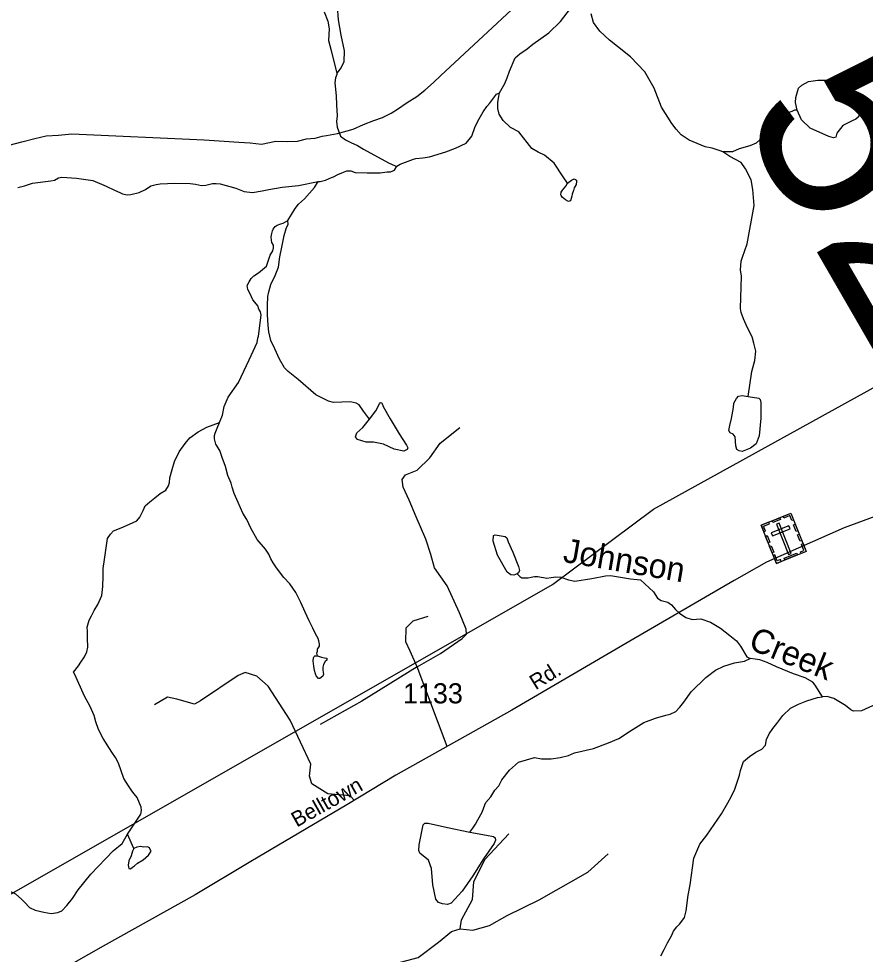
# Model space of a CAD drawing. Extents: x 2056842 to 2160602, y 826753 to 1016856.
# Drawn here: x 2087343 to 2092594, y 896145 to 901949 of the extents above; entities that cross this region are included whole.
import ezdxf

# ---------------------------------------------------------------- set-up
doc = ezdxf.new("R2010")
doc.units = 0
for name, color, linetype in [('Exist Cultural Cemetery CELL', 7, 'Continuous'), ('Exist Hydrographic Creek Single Shore', 7, 'Continuous'), ('Exist Hydrographic Creek Single Shore Label', 7, 'Continuous'), ('Exist Hydrographic Misc Water Feature', 7, 'Continuous'), ('Exist Railroad Mainline', 7, 'Continuous'), ('Exist Road Non-System Type 51', 7, 'Continuous'), ('Exist Road Secondary Structure Standard Bridge Number Label', 7, 'Continuous'), ('Exist Road Secondary Type 51 Attributed', 7, 'Continuous'), ('Exist Road Secondary Type 51 Label', 7, 'Continuous'), ('Exist Road Secondary Type 51 Number Label', 7, 'Continuous'), ('Exist Utilities Electrical Transmission Line', 7, 'Continuous')]:
    doc.layers.add(name, color=color, linetype=linetype)

msp = doc.modelspace()

# ---------------------------------------------------------------- linework, layer by layer
at = {"layer": 'Exist Cultural Cemetery CELL'}
for points in [[(2091948.1, 898806.6), (2092132.9, 898880.6), (2092227.5, 898644.1), (2092042.7, 898570.2)], [(2091964.2, 898766.4), (2091974.7, 898770.6), (2091962.8, 898800.5), (2092000.4, 898815.5), (2091996.3, 898825.9), (2091948.1, 898806.6)], [(2092016.9, 898834.1), (2092065, 898853.3), (2092069.2, 898842.8), (2092021.1, 898823.5)], [(2092149.1, 898840.3), (2092138.6, 898836.1), (2092126.6, 898866), (2092089, 898850.9), (2092084.8, 898861.3), (2092133, 898880.5)], [(2092011.3, 898758.6), (2092018.2, 898741.2), (2092127.5, 898785), (2092120.6, 898802.3)], [(2092060.2, 898819.9), (2092042.9, 898813), (2092118.2, 898624.7), (2092135.5, 898631.6)], [(2092165.7, 898768.2), (2092149.6, 898808.4), (2092160.2, 898812.7), (2092176.2, 898772.5)], [(2091991.7, 898697.5), (2091975.6, 898737.7), (2091986.2, 898742), (2092002.3, 898701.8)], [(2092190.1, 898707), (2092174, 898747.2), (2092184.6, 898751.5), (2092200.7, 898711.2)], [(2092016.7, 898635.1), (2092000.6, 898675.3), (2092011.2, 898679.6), (2092027.3, 898639.3)], [(2092196.8, 898631.8), (2092192.5, 898642.5), (2092212.9, 898650.7), (2092197.9, 898688.2), (2092208.3, 898692.3), (2092227.5, 898644.1)], [(2092073.4, 898582.5), (2092069.1, 898593.2), (2092048.7, 898585), (2092033.7, 898622.5), (2092023.3, 898618.4), (2092042.6, 898570.2)], [(2092091.8, 898602.2), (2092170.6, 898633.7), (2092174.8, 898623.1), (2092096, 898591.6)]]:
    msp.add_lwpolyline(points, close=True, dxfattribs=at)
at = {"layer": 'Exist Hydrographic Creek Single Shore'}
for points in [[(2090325.3, 901488), (2090357.3, 901546.1), (2090373.1, 901582.1), (2090387.1, 901622.2), (2090422.7, 901706.3), (2090450.6, 901730.4), (2090496.6, 901762.5), (2090532.4, 901790.7), (2090631.4, 901861), (2090703.7, 901932.1), (2090833.5, 902103.5), (2090877.1, 902183.6), (2090923.1, 902251.7), (2090956.9, 902297.9), (2090986.8, 902319.9), (2091030.7, 902346), (2091062.5, 902384.2)], [(2089688.9, 901034), (2089709, 901046.1), (2089790.8, 901076.4), (2089806.8, 901080.4), (2089850.5, 901084.9), (2089891.6, 901092.4), (2089992.7, 901123.6), (2090051.3, 901146.1), (2090118.7, 901176), (2090154.3, 901219.5), (2090174, 901279.6), (2090199.8, 901327.7), (2090223.8, 901371.6), (2090245.6, 901403.7), (2090263.6, 901421.8), (2090287.6, 901455.8), (2090307.5, 901479.9), (2090325.3, 901488)], [(2089201.2, 900938.6), (2089213.3, 900938.6), (2089245.1, 900946.7), (2089283.3, 900962.8), (2089295.2, 900966.9), (2089323, 900982.9), (2089357.1, 900997), (2089379, 901005.1), (2089403, 901005.1), (2089429.1, 900995.3), (2089505.1, 900993.4), (2089585.1, 900991.7), (2089629, 900997.8), (2089649.1, 900997.9), (2089673.1, 901008.1), (2089688.9, 901034)], [(2087337.5, 900900.7), (2087377.5, 900912.8), (2087427.3, 900929), (2087541.3, 900943.4), (2087565.3, 900947.4), (2087589.3, 900961.5), (2087609.2, 900965.5), (2087701.3, 900959.9), (2087801.4, 900944.2), (2087885.3, 900909.7), (2087937.7, 900884.7), (2087968.9, 900869.7), (2087986.3, 900862.2), (2088016.3, 900856), (2088037.8, 900858.9), (2088089.7, 900871.1), (2088129.6, 900889.2), (2088161.4, 900911.3), (2088195.5, 900919.4), (2088219.5, 900923.5), (2088310.7, 900928.4), (2088405.5, 900925.9), (2088439.5, 900922.2), (2088476.6, 900914.7), (2088504, 900915.9), (2088543.9, 900927.1), (2088567.6, 900927.1), (2088591.4, 900924.6), (2088689.4, 900896.9), (2088741.5, 900877.2), (2088793.6, 900871.3), (2088853.5, 900881.5), (2088893.5, 900889.6), (2088977.3, 900903.8), (2089079.2, 900914.2), (2089201.2, 900938.6)], [(2092329.5, 897743), (2092284.3, 897814.1), (2092268.3, 897834.1), (2092222.3, 897860), (2092148.3, 897883.9), (2092044.2, 897927.4), (2091986, 897955.5), (2091940.1, 897971.2), (2091912, 897975.1), (2091879.9, 897979)], [(2093100.5, 897591), (2093063, 897610.9), (2093022.8, 897652.5), (2092990.8, 897676.5), (2092936.7, 897692.4), (2092874.5, 897716.3), (2092818.5, 897722), (2092766.6, 897717.9), (2092683.8, 897706.8), (2092570.3, 897654.4), (2092521.6, 897653.1), (2092505.4, 897660.6), (2092471.7, 897688.1), (2092399.4, 897731.7), (2092358.2, 897744.2), (2092329.5, 897743)]]:
    msp.add_lwpolyline(points, dxfattribs=at)
at = {"layer": 'Exist Hydrographic Misc Water Feature'}
msp.add_line((2088056.2, 896801.3), (2088017.9, 896889.3), dxfattribs=at)
for points in [[(2089317.9, 902024.8), (2089324.3, 901940.9), (2089340.5, 901846.9), (2089360.8, 901748.9), (2089358.9, 901681), (2089343.1, 901646.9), (2089315.3, 901610.8)], [(2089238.2, 901990.6), (2089260.1, 901932.7), (2089268.3, 901886.6), (2089264.6, 901812.7), (2089280.8, 901750.7), (2089295, 901690.8), (2089315.3, 901610.8)], [(2091710.5, 901122.3), (2091694.5, 901128.2), (2091644.2, 901146.1), (2091600.4, 901154), (2091502.1, 901195.7), (2091452.1, 901227.5), (2091422, 901263.5), (2091393.9, 901299.4), (2091330.4, 901399.4), (2091284.3, 901516.8), (2091226.9, 901619.1), (2091138.6, 901712.5), (2091056.3, 901776.2), (2091008.4, 901816.1), (2090948.1, 901871.9), (2090908.1, 901925.8), (2090893.7, 901979.7)], [(2089315.3, 901610.8), (2089315.3, 901602.8), (2089307.3, 901582.8), (2089303.4, 901550.8), (2089311.6, 901470.9), (2089313.8, 901414.8), (2089317.9, 901346.8), (2089314, 901310.8), (2089318.1, 901275), (2089338.4, 901219), (2089370.4, 901197), (2089402.6, 901181.1), (2089444.6, 901161.3), (2089480.5, 901139.4), (2089636.8, 901053.9), (2089677, 901036.1), (2089688.9, 901034)], [(2092171.3, 901381.8), (2092161.7, 901429.1), (2092162.8, 901460.1), (2092179.9, 901517.7), (2092201.2, 901536.9), (2092241.8, 901559.4), (2092299.4, 901566.8), (2092404, 901567.9), (2092428.5, 901560.4), (2092464.8, 901527.3), (2092539.5, 901428), (2092556.6, 901393.9), (2092558.7, 901371.4), (2092552.3, 901340.5), (2092536.3, 901324.5), (2092512.8, 901315.9), (2092455.2, 901286), (2092417.8, 901239), (2092412.5, 901213.4), (2092397.6, 901209.1), (2092367.7, 901217.7), (2092252.4, 901270), (2092198, 901321.3), (2092171.3, 901381.8)], [(2090747.8, 900929.2), (2090719.9, 900967.1), (2090665.1, 901051.9), (2090604.6, 901102.9), (2090564.6, 901120.8), (2090526.5, 901142.7), (2090444.3, 901246.4), (2090394, 901274.2), (2090347.9, 901318), (2090323.7, 901356), (2090315.7, 901391.9), (2090315.7, 901428), (2090319.6, 901456), (2090325.3, 901488)], [(2092171.3, 901381.8), (2092155.6, 901381.7), (2092139.4, 901373.7), (2092119.7, 901367.5), (2092095.8, 901357.5), (2092075.7, 901341.5), (2092027.9, 901295.4), (2091997.9, 901259.2), (2091968, 901221.1), (2091918.2, 901176.9), (2091878.2, 901160.8), (2091812.4, 901140.6), (2091770.3, 901122.5), (2091710.5, 901122.3)], [(2091867.1, 899605.8), (2091890.8, 899759.4), (2091908.2, 899828), (2091916.1, 899887.2), (2091902, 899935), (2091891.9, 899975), (2091873.7, 900010.9), (2091855.6, 900048.8), (2091839.4, 900086.8), (2091823.4, 900126.8), (2091819.3, 900150.8), (2091825.9, 900351.7), (2091819.7, 900390.4), (2091823.4, 900444.1), (2091833.4, 900470.3), (2091862.1, 900551.4), (2091904.5, 900790.1), (2091895.8, 900888.7), (2091887, 900948.6), (2091852.1, 901017.2), (2091823.4, 901055.9), (2091754.6, 901094.4), (2091710.5, 901122.3)], [(2089012, 900696), (2089057.7, 900772.2), (2089077.6, 900798.1), (2089115.5, 900832.2), (2089177.5, 900902.5), (2089201.2, 900938.6)], [(2090747.8, 900929.2), (2090771.8, 900947.3), (2090787.8, 900955.3), (2090795.8, 900951.3), (2090803.8, 900947.3), (2090803.8, 900939.3), (2090799.9, 900919.3), (2090788, 900899.2), (2090783.9, 900883.2), (2090776.1, 900859.2), (2090774, 900847.3), (2090766.3, 900819.3), (2090754.2, 900815.2), (2090734.3, 900825.1), (2090714.2, 900841.1), (2090708, 900851), (2090706, 900857), (2090708, 900873.1), (2090716, 900885.1), (2090735.9, 900909.2), (2090747.8, 900929.2)], [(2088587.9, 899442.8), (2088606.5, 899489.8), (2088617.8, 899543.4), (2088642.2, 899601.1), (2088705.8, 899692.2), (2088773.2, 899832), (2088822.5, 899939.5), (2088826.2, 899967.4), (2088830.3, 899979.5), (2088845.9, 900109.5), (2088841.8, 900129.5), (2088831.7, 900147.5), (2088825.6, 900167.5), (2088807.7, 900189.4), (2088795.7, 900205.4), (2088777.4, 900241.3), (2088763.5, 900269.3), (2088759.4, 900293.3), (2088771.2, 900317.3), (2088785.2, 900337.4), (2088801.2, 900353.4), (2088829.1, 900371.5), (2088878.9, 900413.5), (2088902.7, 900481.6), (2088918.7, 900507.7), (2088922.6, 900527.7), (2088922.6, 900543.7), (2088912.5, 900559.7), (2088910.5, 900575.7), (2088908.2, 900595.6), (2088912.3, 900615.7), (2088916.2, 900631.7), (2088920.1, 900643.7), (2088934.3, 900659.8), (2088946.2, 900667.8), (2088968.1, 900675.8), (2088984.1, 900679.9), (2089012, 900696)], [(2089518.9, 899463.8), (2089481.5, 899513.7), (2089454, 899552.4), (2089435.3, 899563.7), (2089397.9, 899572.4), (2089295.6, 899568.9), (2089263.4, 899576.9), (2089185.2, 899614.7), (2089077, 899710.2), (2089045, 899736.1), (2089014.9, 899760), (2088990.9, 899782), (2088960.7, 899835.9), (2088930.6, 899901.8), (2088906.4, 899951.7), (2088894.3, 900005.7), (2088890, 900045.7), (2088885.9, 900113.6), (2088885.7, 900169.6), (2088887.5, 900225.6), (2088893.5, 900253.6), (2088907.4, 900299.7), (2088933, 900355.8), (2088955, 900407.8), (2088962.8, 900471.9), (2088974.5, 900531.8), (2088988.4, 900603.9), (2089004.2, 900654), (2089014, 900672), (2089012, 900696)], [(2091867.1, 899605.8), (2091934.4, 899594.1), (2091943.2, 899586.6), (2091946.9, 899567.9), (2091945.7, 899470.5), (2091936.9, 899362), (2091917, 899310.8), (2091883.3, 899284.6), (2091830.9, 899264.6), (2091812.2, 899267.1), (2091797.2, 899275.8), (2091792.2, 899298.3), (2091787.2, 899355.7), (2091774.8, 899370.7), (2091756.1, 899380.7), (2091747.3, 899394.4), (2091754.8, 899424.4), (2091763.5, 899469.3), (2091777.3, 899536.7), (2091779.8, 899562.9), (2091794.7, 899592.9), (2091807.2, 899606.6), (2091830.9, 899610.3), (2091867.1, 899605.8)], [(2089518.9, 899463.8), (2089558.8, 899516.2), (2089580, 899558.7), (2089586.3, 899567.4), (2089595, 899564.9), (2089602.5, 899542.4), (2089647.4, 899466.3), (2089703.5, 899373.9), (2089748.4, 899304.1), (2089755.9, 899286.6), (2089753.4, 899276.6), (2089732.2, 899266.6), (2089672.3, 899279.1), (2089606.2, 899309), (2089543.9, 899322.8), (2089497.7, 899321.5), (2089444.1, 899337.8), (2089431.6, 899354), (2089439.1, 899378.9), (2089476.5, 899412.6), (2089518.9, 899463.8)], [(2088017.9, 896889.3), (2088099.5, 897013.5), (2088103.4, 897037.6), (2088101.3, 897057.4), (2088077.1, 897117.4), (2088059.1, 897141.3), (2088045.2, 897159.4), (2088022.7, 897190.9), (2087995.3, 897234.6), (2087962.5, 897331), (2087942.4, 897364.9), (2087920.3, 897398.9), (2087866.1, 897482.7), (2087837.9, 897538.6), (2087821.9, 897586.6), (2087809.8, 897626.5), (2087785.6, 897682.4), (2087751.3, 897746.3), (2087691, 897880.1), (2087682.8, 897896.1), (2087712.8, 897934.2), (2087728.8, 897958.2), (2087750.5, 897990.2), (2087764.4, 898022.3), (2087770.4, 898050.3), (2087770.2, 898106.3), (2087770, 898150.4), (2087767.9, 898174.4), (2087779.8, 898218.3), (2087793.8, 898244.4), (2087811.6, 898278.4), (2087833.5, 898314.5), (2087857.3, 898370.6), (2087865.1, 898426.6), (2087867, 898490.6), (2087866.8, 898538.6), (2087874.8, 898594.6), (2087894.2, 898724.6), (2087912.3, 898750.8), (2087930.1, 898772.8), (2087978.1, 898791), (2088030, 898813.1), (2088075.9, 898833.2), (2088093.8, 898857.3), (2088113.6, 898897.4), (2088127.6, 898927.4), (2088155.5, 898951.5), (2088187.5, 898975.5), (2088219.2, 899003.7), (2088255.3, 899023.8), (2088271.1, 899051.8), (2088277.3, 899071.9), (2088279.1, 899099.9), (2088294.9, 899152), (2088308.7, 899201.9), (2088338.6, 899262), (2088374.5, 899314.1), (2088404.2, 899348.3), (2088456.1, 899386.3), (2088510, 899414.5), (2088587.9, 899442.8)], [(2089196.5, 897996.8), (2089192.2, 898012.8), (2089196.3, 898024.8), (2089196.3, 898036.8), (2089208.2, 898056.9), (2089208.2, 898068.9), (2089204.1, 898088.8), (2089200, 898104.7), (2089184, 898132.7), (2089167.8, 898168.6), (2089143.6, 898212.6), (2089119.6, 898266.5), (2089093.4, 898326.4), (2089061.2, 898388.3), (2089025.1, 898442.3), (2088987, 898482.1), (2088942.7, 898542), (2088920.5, 898573.9), (2088906.6, 898597.9), (2088894.5, 898627.8), (2088874.4, 898657.8), (2088822.1, 898717.5), (2088781.9, 898789.4), (2088757.7, 898841.4), (2088733.7, 898881.3), (2088703.4, 898947.2), (2088679.4, 899003.1), (2088667.1, 899043.1), (2088661.1, 899067.1), (2088640.8, 899114.9), (2088624.8, 899170.9), (2088604.7, 899226.9), (2088590.6, 899270.8), (2088566.4, 899308.7), (2088556.4, 899342.6), (2088556.1, 899362.6), (2088560.3, 899376.7), (2088574, 899408.8), (2088587.9, 899442.8)], [(2090434.6, 898504.6), (2090414.6, 898497.2), (2090394.6, 898498.5), (2090373.4, 898516), (2090312.3, 898620.8), (2090286.1, 898708.2), (2090287.3, 898741.9), (2090298.6, 898746.9), (2090334.8, 898740.6), (2090359.7, 898736.9), (2090370.9, 898728.1), (2090378.4, 898703.2), (2090408.4, 898639.5), (2090443.3, 898549.7), (2090449.5, 898525.9), (2090443.3, 898511), (2090434.6, 898504.6)], [(2090434.6, 898504.6), (2090442.6, 898496.6), (2090450.6, 898488.6), (2090462.7, 898480.7), (2090478.7, 898480.7), (2090502.7, 898480.8), (2090522.6, 898484.9), (2090542.7, 898488.9), (2090562.6, 898489), (2090582.7, 898485.1), (2090598.7, 898483.2), (2090618.8, 898479.2), (2090646.7, 898483.3), (2090674.7, 898487.4), (2090706.7, 898483.5), (2090752.9, 898467.6), (2090792.9, 898459.7), (2090898.7, 898476.1), (2090982.7, 898492.3), (2091014.7, 898494.3), (2091138.6, 898474.9), (2091200.7, 898467), (2091252.8, 898419.2), (2091280.9, 898393.3), (2091305.1, 898353.4), (2091329.1, 898339.4), (2091369.1, 898329.5), (2091393.2, 898313.6), (2091417.2, 898283.8), (2091441.2, 898261.8), (2091481.4, 898233.9), (2091519.4, 898222), (2091573.5, 898226.2), (2091633.4, 898204.4), (2091695.5, 898168.6), (2091753.7, 898122.8), (2091795.8, 898088.9), (2091820, 898057), (2091859.9, 897991), (2091880.2, 897979.2)], [(2089196.5, 897996.8), (2089220.5, 897988.9), (2089240.4, 897984.9), (2089254.4, 897981), (2089254.4, 897969), (2089244.5, 897961), (2089232.6, 897943), (2089228.5, 897927), (2089228.7, 897906.9), (2089232.6, 897882.9), (2089228.7, 897870.9), (2089210.9, 897856.8), (2089202.9, 897856.8), (2089188.7, 897872.8), (2089184.6, 897884.8), (2089176.6, 897904.7), (2089172.5, 897932.7), (2089168.4, 897964.7), (2089170.5, 897984.7), (2089176.4, 897992.7), (2089180.3, 897996.7), (2089196.5, 897996.8)], [(2090141.4, 896902.1), (2090159.5, 896928), (2090175.4, 896951.9), (2090191.4, 896979.9), (2090217.3, 897026.1), (2090233.3, 897072.1), (2090241.1, 897086.2), (2090271, 897122.2), (2090296.8, 897162.3), (2090320.8, 897190.3), (2090338.7, 897226.4), (2090386.4, 897286.6), (2090442.2, 897336.7), (2090542.1, 897365), (2090586.2, 897357.2), (2090646.2, 897357.3), (2090702.2, 897365.5), (2090752.3, 897377.7), (2090790, 897393.8), (2090907.9, 897422.2), (2091001.8, 897456.5), (2091065.8, 897482.7), (2091137.6, 897530.9), (2091221.4, 897583.1), (2091293.4, 897609.3), (2091357.4, 897627.6), (2091383.2, 897635.6), (2091419.1, 897651.8), (2091443.1, 897677.8), (2091469.1, 897709.9), (2091514.8, 897774), (2091604.5, 897862.4), (2091664.3, 897906.6), (2091716.2, 897932.6), (2091782.2, 897952.8), (2091844.2, 897963.1), (2091880.2, 897979.2)], [(2091326, 896135.6), (2091347.7, 896175.7), (2091367.6, 896215.7), (2091391.6, 896259.8), (2091405.3, 896287.9), (2091425.2, 896316), (2091441.2, 896332), (2091457.2, 896350), (2091473.2, 896374.1), (2091482.6, 896413.8), (2091496.4, 896512.4), (2091508.8, 896576.1), (2091530, 896741.3), (2091567.5, 896828.7), (2091611.1, 896883.6), (2091703.2, 897017.2), (2091741.9, 897084.3), (2091764.3, 897125.5), (2091785.5, 897169.2), (2091798.6, 897213), (2091814.4, 897257.1), (2091820.4, 897285.1), (2091838, 897341), (2091875.9, 897371.2), (2091915.9, 897399.4), (2091951.8, 897417.4), (2091975.8, 897441.5), (2091981.7, 897477.5), (2091997.5, 897511.6), (2092021.3, 897545.7), (2092045.3, 897575.7), (2092083.3, 897625.8), (2092131, 897672), (2092180.9, 897696.2), (2092230.9, 897716.3), (2092298.8, 897738.4), (2092329.5, 897743)], [(2090141.4, 896902.1), (2090243.7, 896883.4), (2090287.3, 896875.9), (2090298.6, 896867.1), (2090301.1, 896852.2), (2090291.1, 896832.2), (2090225, 896737.3), (2090158.9, 896631.2), (2090092.7, 896537.6), (2090025.4, 896461.5), (2090001.7, 896454), (2089971.7, 896457.8), (2089946.8, 896466.5), (2089930.6, 896487.7), (2089911.9, 896576.3), (2089903.1, 896677.4), (2089884.4, 896728.6), (2089830.8, 896772.3), (2089824.6, 896788.5), (2089825.8, 896824.7), (2089852, 896948.3), (2089862, 896958.3), (2089881.9, 896958.3), (2090001.7, 896930.8), (2090141.4, 896902.1)], [(2087267, 896540.9), (2087283, 896539), (2087323.2, 896521.1), (2087361.3, 896485.2), (2087381.4, 896467.3), (2087409.5, 896435.3), (2087445.4, 896419.5), (2087497.5, 896405.7), (2087543.6, 896397.8), (2087585.4, 896403.9), (2087609.4, 896414), (2087641.4, 896448.1), (2087675.2, 896492.2), (2087711.1, 896544.3), (2087790.7, 896642.8), (2087928.3, 896787), (2087984.1, 896833.1), (2088017.9, 896889.3)], [(2088056.2, 896801.3), (2088048.2, 896785.3), (2088044.3, 896771.3), (2088040.2, 896755.3), (2088026.5, 896725.3), (2088020.6, 896697.3), (2088022.6, 896687.2), (2088024.7, 896677.3), (2088036.5, 896675.3), (2088048.6, 896685.4), (2088060.5, 896693.4), (2088080.4, 896709.5), (2088114.5, 896731.6), (2088148.3, 896759.6), (2088164.1, 896785.6), (2088160.2, 896791.7), (2088154.2, 896805.7), (2088142.1, 896811.6), (2088118.2, 896809.5), (2088098.3, 896813.5), (2088074.3, 896809.4), (2088056.2, 896801.3)]]:
    msp.add_lwpolyline(points, dxfattribs=at)
at = {"layer": 'Exist Railroad Mainline'}
for points in [[(2089652.2, 901362.5), (2089692.1, 901386.4), (2089752, 901428.8), (2089812, 901465), (2089861.8, 901505.2), (2089915.6, 901553.2), (2089961.5, 901595.3), (2090691.2, 902275.5)], [(2087513, 901221.7), (2087589.1, 901225.9), (2087672.9, 901234.2), (2088492.9, 901196.8), (2088617, 901189.2), (2088708.9, 901183.5), (2088779, 901177.7), (2088849, 901169.9), (2088937, 901188.2), (2089009, 901186.3), (2089072.8, 901188.6), (2089128.9, 901202.9), (2089180.8, 901207), (2089224.8, 901219.1), (2089252.8, 901225.1), (2089320.6, 901237.3), (2089416.6, 901263.7), (2089480.6, 901291.8), (2089546.5, 901318), (2089600.3, 901336.3), (2089652.2, 901362.5)], [(2087283.2, 901165), (2087361.2, 901185.2), (2087443, 901205.5), (2087513, 901221.7)]]:
    msp.add_lwpolyline(points, dxfattribs=at)
at = {"layer": 'Exist Road Non-System Type 51'}
msp.add_line((2089999.5, 897434.3), (2089815.3, 897927.6), dxfattribs=at)
for points in [[(2089815.3, 897927.6), (2089959.1, 898010.3), (2090094.6, 898104.2), (2090120, 898131.1), (2090118.5, 898162.4), (2090076.8, 898263.7), (2090001.5, 898429.9), (2089922.6, 898541.7), (2089900.2, 898625.2), (2089869, 898720.6), (2089807.9, 898859.2), (2089765.4, 898962.8), (2089726.7, 899041.8), (2089722.2, 899091), (2089741.6, 899119.3), (2089814.6, 899149.1), (2089893.5, 899225.1), (2089957.6, 899314.6), (2090079, 899413.7)], [(2089815.3, 897927.6), (2089771.4, 898025.2), (2089744.6, 898083.4), (2089746.1, 898169.8), (2089789.3, 898213), (2089883.1, 898242.8)], [(2089815.3, 897927.6), (2089472, 897715.2), (2089213.6, 897569.8)], [(2089424.4, 897101.1), (2089399, 897127.9), (2089260.5, 897141.3), (2089209.8, 897171.1), (2089160.7, 897202.4), (2089145.8, 897250.1), (2089154.7, 897324.6), (2089027.4, 897596.7), (2088890.3, 897808.3), (2088819.6, 897870.2), (2088748.1, 897892.6), (2088704.9, 897874.7), (2088471, 897716.7), (2088433.8, 897697.3), (2088323.5, 897728.6), (2088265.4, 897740.5), (2088185, 897692.8)], [(2090080.5, 896302.9), (2090088.7, 896358.7), (2090157.2, 896484), (2090166.1, 896594.3), (2090234.7, 896732.9), (2090382.1, 896892.4)], [(2090080.5, 896302.9), (2090159.4, 896293.9), (2090262.2, 896323.7), (2090372.4, 896384.8), (2090572, 896483.2), (2090873.7, 896655.4), (2091000.3, 896768.7)], [(2088929, 895898.9), (2089042.3, 895971.9), (2089109.3, 895973.4), (2089305.9, 895958.5), (2089426.6, 896004.7), (2089679, 896089), (2089820.6, 896124.7), (2089947.2, 896220.1), (2090026.9, 896286.5), (2090080.5, 896302.9)]]:
    msp.add_lwpolyline(points, dxfattribs=at)
at = {"layer": 'Exist Road Secondary Type 51 Attributed'}
msp.add_lwpolyline([(2097584.5, 901381.1), (2097440.8, 901258.9), (2097275.5, 901120.4), (2097046.5, 900979.3), (2096312.6, 900635.1), (2095454.9, 900254.9), (2094879.1, 899939.4), (2094260.3, 899562.8), (2093814.7, 899296.7), (2093533.6, 899171.8), (2092778.2, 898906.6), (2092463.9, 898789.7), (2091981.5, 898576.7), (2091780.3, 898463.5), (2091132.7, 898086.9), (2090400.7, 897659.9), (2089683, 897256.3), (2089377.6, 897073), (2088782.1, 896719.7), (2088437.2, 896513), (2087866.9, 896195.7), (2087516.6, 895996.1), (2087189.6, 895823.6)], dxfattribs=at)
at = {"layer": 'Exist Utilities Electrical Transmission Line'}
msp.add_lwpolyline([(2081456.5, 893335.6), (2082215.8, 893541.9), (2083698.6, 894464.4), (2090653.3, 898439.9), (2091279.8, 898905.8), (2093655.2, 900217), (2093986.6, 900420.2), (2096731, 902082.7)], dxfattribs=at)

# ---------------------------------------------------------------- texts
at = {"layer": 'Exist Hydrographic Creek Single Shore Label'}
for s, rotation, p in [('Johnson', 350.31708, (2090713.7, 898579.5)), ('Creek', 338.05744, (2091862.4, 898042.4))]:
    msp.add_text(s, height=150, rotation=rotation, dxfattribs=at).set_placement(p)
at = {"layer": 'Exist Road Secondary Structure Standard Bridge Number Label'}
msp.add_text('52', height=1230.31, rotation=300, dxfattribs=at).set_placement((2091795.8, 901363.6))
at = {"layer": 'Exist Road Secondary Type 51 Label'}
for s, rotation, p in [('Rd.', 31.81219, (2090549.2, 897781.7)), ('Belltown', 29.41843, (2089067.5, 896930.8))]:
    msp.add_text(s, height=95, rotation=rotation, dxfattribs=at).set_placement(p)
at = {"layer": 'Exist Road Secondary Type 51 Number Label'}
msp.add_text('1133', height=125, dxfattribs=at).set_placement((2089726.1, 897701.4))

doc.saveas('drawing.dxf')
